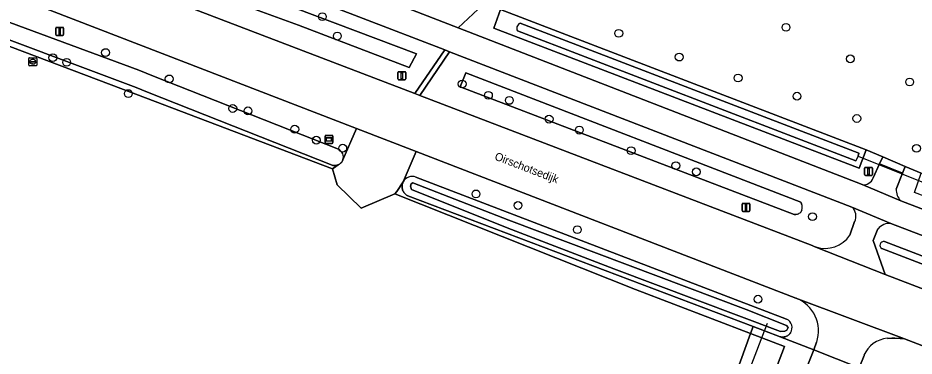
# Model space of a CAD drawing. Extents: x 155209 to 156748, y 385356 to 388487.
# Drawn here: x 155768.7 to 155880.6, y 386668.2 to 386710.5 of the extents above; entities that cross this region are included whole.
import ezdxf

# ---------------------------------------------------------------- set-up
doc = ezdxf.new("R2010")
doc.units = 0
for name, color, linetype in [('IMGEO_Afsluitpaal', 7, 'Continuous'), ('IMGEO_Berm_groen', 7, 'Continuous'), ('IMGEO_Boom', 7, 'Continuous'), ('IMGEO_Brandkraan', 7, 'Continuous'), ('IMGEO_Duiker', 7, 'Continuous'), ('IMGEO_Erf', 7, 'Continuous'), ('IMGEO_Fietspad_gesloten', 7, 'Continuous'), ('IMGEO_Gemengd_bos', 7, 'Continuous'), ('IMGEO_Groenvoorziening', 7, 'Continuous'), ('IMGEO_Haag', 7, 'Continuous'), ('IMGEO_Hek', 7, 'Continuous'), ('IMGEO_Lichtmast', 7, 'Continuous'), ('IMGEO_Oever', 7, 'Continuous'), ('IMGEO_Openbare_ruimte_label', 7, 'Continuous'), ('IMGEO_Rijbaan_lokaal_gesloten', 7, 'Continuous'), ('IMGEO_Rijbaan_lokaal_open', 7, 'Continuous'), ('IMGEO_Verkeersbordpaal', 7, 'Continuous'), ('IMGEO_Verklikker', 7, 'Continuous'), ('IMGEO_Voetpad_gesloten', 7, 'Continuous'), ('IMGEO_Voetpad_open', 7, 'Continuous'), ('IMGEO_Waterloop', 7, 'Continuous')]:
    doc.layers.add(name, color=color, linetype=linetype)

msp = doc.modelspace()

# ---------------------------------------------------------------- linework, layer by layer
at = {"layer": 'IMGEO_Afsluitpaal'}
for p, q in [((155773.4, 386708.38), (155773.4, 386709.18)), ((155773.4, 386709.18), (155773.4, 386708.38)), ((155773.5, 386709.28), (155774.29, 386709.28)), ((155774.29, 386709.28), (155773.5, 386709.28)), ((155774.39, 386709.18), (155774.39, 386708.38)), ((155774.39, 386708.38), (155774.39, 386709.18)), ((155774.29, 386708.28), (155773.5, 386708.28)), ((155773.5, 386708.28), (155774.29, 386708.28))]:
    msp.add_line(p, q, dxfattribs=at)
msp.add_lwpolyline([(155773.82, 386709.16), (155773.97, 386709.16), (155773.97, 386708.41), (155773.82, 386708.41), (155773.82, 386709.16)], dxfattribs=at)
for centre, start, end in [((155773.5, 386709.18), 90, 180), ((155773.5, 386709.18), 90, 180), ((155774.29, 386709.18), 0, 90), ((155774.29, 386709.18), 360, 90), ((155773.5, 386708.38), 180, 270), ((155773.5, 386708.38), 180, 270), ((155774.29, 386708.38), 270, 0), ((155774.29, 386708.38), 270, 0)]:
    msp.add_arc(centre, 0.1, start, end, dxfattribs=at)
at = {"layer": 'IMGEO_Berm_groen'}
msp.add_lwpolyline([(155793.53, 386723.81), (155782.08, 386727.97), (155782.52, 386725.2), (155792.56, 386721.3), (155823.67, 386709.23), (155826.78, 386712.15), (155820.02, 386714.17)], close=True, dxfattribs=at)
for points in [[(155787.54, 386712.8), (155818.26, 386701.02), (155821.98, 386706.46), (155791.39, 386718.27)], [(155785.57, 386717.88), (155790.57, 386716.13), (155803.21, 386711.7), (155818.46, 386705.97), (155817.55, 386704.28), (155803.73, 386709.57), (155789.98, 386714.61), (155785.11, 386716.4)], [(155786.7, 386706.02), (155761.51, 386715.74), (155760.31, 386714.85), (155759.25, 386713.89), (155758.81, 386713.23), (155761.07, 386712.32), (155761.11, 386712.3), (155783.77, 386703.93), (155785.63, 386703.2), (155808.7, 386694.05)], [(155828.93, 386711.51), (155826.78, 386712.15), (155823.67, 386709.23), (155874.11, 386689.65)], [(155875.47, 386690.48), (155876.27, 386692.22), (155876.68, 386693.11), (155874.62, 386693.99), (155873.73, 386691.68), (155828.11, 386709.2), (155828.93, 386711.51)], [(155809.25, 386692.73), (155810.97, 386696.65), (155786.7, 386706.02)], [(155822.58, 386706.23), (155818.86, 386700.79), (155867.85, 386682.04), (155868.04, 386681.96), (155868.31, 386681.85)], [(155872.83, 386686.83), (155822.58, 386706.23)], [(155823.91, 386701.84), (155824.61, 386703.6), (155866.46, 386687.43), (155866.53, 386687.24)], [(155866.02, 386685.97), (155865.81, 386685.92), (155865.6, 386685.89), (155823.91, 386701.84)], [(155996.82, 386644.23), (155997.61, 386646.44), (155990.99, 386649.3), (155990.06, 386646.73), (155916.52, 386675.03), (155880.66, 386688.65), (155881.47, 386691.06), (155879.46, 386691.92), (155879.13, 386691.08), (155878.35, 386689.08)], [(155878.92, 386687.63), (155990.49, 386644.88), (155995.68, 386642.88), (156000, 386641.23), (156053.62, 386620.73), (156114.7, 386597.38), (156119.19, 386595.66), (156120.94, 386594.79), (156129.23, 386591.35), (156138.31, 386587.8), (156143.99, 386585.35), (156148.25, 386583.66), (156152.28, 386581.93), (156156.65, 386579.82), (156158.6, 386579.01), (156159.45, 386578.78)], [(155866.57, 386686.46), (155866.44, 386686.22)], [(155872.58, 386683.33), (155873.16, 386685.03)], [(155989.46, 386642), (155916.39, 386670), (155877.68, 386684.79)], [(155876.08, 386684.11), (155875.47, 386682.66), (155876.97, 386678.42), (155984.6, 386637.22), (155985.42, 386636.89)], [(155876.88, 386682.53), (155987.28, 386640.17)], [(155987.28, 386640.17), (155986.9, 386639.25), (155876.58, 386681.66)]]:
    msp.add_lwpolyline(points, dxfattribs=at)
for centre, radius, start, end in [((155808.25, 386693.09), 1.07, 340.1832, 65.3376), ((155874.31, 386690.84), 1.21, 260.3353, 342.3942), ((155880.37, 386689.04), 2.03, 178.787, 224.1206), ((155865.38, 386686.79), 1.24, 344.5264, 21.3449), ((155871.8, 386685.71), 1.53, 333.3914, 47.2183), ((155865.84, 386686.76), 0.808, 282.5183, 318.1779), ((155877.52, 386682.96), 1.84, 84.9359, 141.3575), ((155869.46, 386685.43), 3.76, 252.1502, 325.9482), ((155876.79, 386682.07), 0.464, 79.3375, 242.4891)]:
    msp.add_arc(centre, radius, start, end, dxfattribs=at)
at = {"layer": 'IMGEO_Boom'}
for centre in [(155806.7, 386710.61), (155864.6, 386709.28), (155808.56, 386708.19), (155843.71, 386708.54), (155773.04, 386705.49), (155779.62, 386706.13), (155851.26, 386705.57), (155872.62, 386705.35), (155774.77, 386704.92), (155787.57, 386702.84), (155824.15, 386702.21), (155858.61, 386702.95), (155880.03, 386702.46), (155782.46, 386701.01), (155827.43, 386700.79), (155830.04, 386700.16), (155865.97, 386700.68), (155795.51, 386699.15), (155797.41, 386698.85), (155835.01, 386697.82), (155873.44, 386697.9), (155803.25, 386696.56), (155838.78, 386696.45), (155805.95, 386695.19), (155809.24, 386694.19), (155880.89, 386694.17), (155845.25, 386693.88), (155850.84, 386692.01), (155853.39, 386691.24), (155825.88, 386688.48), (155831.12, 386687.04), (155867.9, 386685.64), (155838.53, 386684.01), (155861.1, 386675.33)]:
    msp.add_circle(centre, 0.489, dxfattribs=at)
at = {"layer": 'IMGEO_Brandkraan'}
for p, q in [((155770.04, 386704.56), (155770.04, 386705.41)), ((155770.11, 386705.49), (155770.96, 386705.49)), ((155770.3, 386704.98), (155770.3, 386704.99)), ((155770.34, 386705.03), (155770.74, 386705.03)), ((155770.73, 386704.94), (155770.34, 386704.94)), ((155770.55, 386704.71), (155770.52, 386704.71)), ((155770.53, 386705.27), (155770.55, 386705.27)), ((155770.78, 386704.99), (155770.78, 386704.98)), ((155771.04, 386705.41), (155771.04, 386704.56)), ((155770.96, 386704.49), (155770.11, 386704.49))]:
    msp.add_line(p, q, dxfattribs=at)
for points in [[(155770.04, 386704.56), (155770.04, 386705.41)], [(155770.11, 386705.49), (155770.96, 386705.49)], [(155771.04, 386705.41), (155771.04, 386704.56)], [(155770.96, 386704.49), (155770.11, 386704.49)]]:
    msp.add_lwpolyline(points, dxfattribs=at)
for centre, radius, start, end in [((155770.11, 386705.41), 0.0765, 91.552, 178.448), ((155770.11, 386705.41), 0.0765, 91.552, 178.448), ((155770.34, 386704.99), 0.0403, 85.8775, 175.7526), ((155770.33, 386704.98), 0.0366, 178.938, 274.7102), ((155770.74, 386704.99), 0.043, 264.8664, 352.4533), ((155770.74, 386704.99), 0.0386, 1.7309, 96.639), ((155770.96, 386705.41), 0.0765, 1.552, 88.448), ((155770.96, 386705.41), 0.0765, 1.552, 88.448), ((155770.11, 386704.56), 0.0765, 181.552, 268.448), ((155770.11, 386704.56), 0.0765, 181.552, 268.448), ((155770.96, 386704.56), 0.0765, 271.552, 358.448), ((155770.96, 386704.56), 0.0765, 271.552, 358.448)]:
    msp.add_arc(centre, radius, start, end, dxfattribs=at)
for centre, major_axis, ratio, start_param, end_param in [((155770.52, 386704.99), (-0.387, 0.002), 0.722429, 4.712389, 7.853982), ((155770.55, 386704.99), (-0.39, 0.002), 0.717154, 1.570796, 4.712389)]:
    msp.add_ellipse(centre, major_axis=major_axis, ratio=ratio, start_param=start_param, end_param=end_param, dxfattribs=at)
at = {"layer": 'IMGEO_Duiker'}
for points in [[(155873.6, 386693.18), (155881.97, 386689.81)], [(155859.83, 386665.97), (155860.33, 386667.27), (155861.92, 386671.39), (155862.29, 386672.35)]]:
    msp.add_lwpolyline(points, dxfattribs=at)
at = {"layer": 'IMGEO_Erf'}
msp.add_lwpolyline([(155827.24, 386584.98), (155828.63, 386588.62), (155831.1, 386595.08), (155832.48, 386598.7), (155858.39, 386666.09), (155860.17, 386671.06), (155845.78, 386676.56), (155815.75, 386688.47), (155811.53, 386686.69), (155808.55, 386689.62), (155807.95, 386691.6), (155784.6, 386700.46), (155766.42, 386707.35), (155764.8, 386707.96), (155764.04, 386705.95)], dxfattribs=at)
at = {"layer": 'IMGEO_Fietspad_gesloten'}
for points in [[(155717.68, 386750), (155664.94, 386770.25), (155663.89, 386767.51), (155697.56, 386754.39), (155708.95, 386750), (155761.76, 386729.68), (155766.81, 386727.74), (155777.37, 386723.68), (155783.26, 386721.41), (155791.39, 386718.27), (155821.98, 386706.46), (155822.58, 386706.23), (155872.83, 386686.83), (155877.68, 386684.79), (155916.39, 386670), (155989.46, 386642), (155994.28, 386640.16), (156000, 386637.97), (156052.47, 386617.83), (156121.21, 386591.61), (156131.18, 386587.42), (156137.33, 386584.91), (156141.25, 386583.25)], [(156000, 386641.23), (155995.68, 386642.88), (155990.49, 386644.88), (155878.92, 386687.63), (155874.11, 386689.65), (155823.67, 386709.23), (155792.56, 386721.3), (155782.52, 386725.2), (155777.32, 386727.1), (155717.68, 386750)]]:
    msp.add_lwpolyline(points, dxfattribs=at)
at = {"layer": 'IMGEO_Gemengd_bos'}
msp.add_lwpolyline([(156143.42, 386614.27), (156125.24, 386621.36), (155846.72, 386730.89), (155826.78, 386712.15), (155828.93, 386711.51), (155874.62, 386693.99), (155876.68, 386693.11), (155879.46, 386691.92), (155881.47, 386691.06), (155990.99, 386649.3), (155997.61, 386646.44), (156055.03, 386624.31), (156120.56, 386599.32), (156137.65, 386592.62), (156152.92, 386586.26), (156153.55, 386590.46), (156160.78, 386591.55), (156161.17, 386595.64), (156158.22, 386609.07), (156157.32, 386608.64), (156155.98, 386609.71)], close=True, dxfattribs=at)
at = {"layer": 'IMGEO_Groenvoorziening'}
for points in [[(155761.07, 386712.32), (155758.81, 386713.23), (155757.43, 386711.59), (155756.9, 386710.96), (155758.83, 386710.23), (155764.8, 386707.96), (155766.42, 386707.35), (155784.6, 386700.46), (155807.95, 386691.6), (155808.36, 386691.89), (155808.67, 386692.1), (155808.59, 386692.07), (155808.5, 386692.05), (155808.4, 386692.03), (155808.31, 386692.02), (155808.21, 386692.02), (155808.12, 386692.03), (155808.02, 386692.04), (155807.93, 386692.07), (155784.87, 386701.18)], [(155784.87, 386701.18), (155783.45, 386701.75), (155760.2, 386710.46)], [(155865.84, 386675.47), (155818.43, 386693.77), (155816.8, 386689.98)], [(155818.38, 386690.59), (155864.67, 386672.83)], [(155855.14, 386636.42), (155852.27, 386637.56), (155864.42, 386669.44), (155860.17, 386671.06), (155858.39, 386666.09)], [(155865.17, 386671.16), (155865.14, 386671.11), (155865.08, 386671.03), (155865.01, 386670.95), (155864.93, 386670.88), (155864.85, 386670.82), (155864.76, 386670.76), (155864.67, 386670.71), (155864.57, 386670.67), (155864.47, 386670.64), (155864.37, 386670.62), (155864.27, 386670.61), (155864.16, 386670.61), (155864.06, 386670.61), (155863.95, 386670.63), (155863.85, 386670.65), (155868.05, 386669), (155868.42, 386669.95)], [(156047.62, 386605.62), (156000, 386623.97), (155879.41, 386670.4), (155878.87, 386670.44), (155878.19, 386670.47), (155877.79, 386670.47), (155877.25, 386670.44)], [(155874.34, 386668.32), (155873.72, 386666.78), (155876.16, 386665.82), (155876.08, 386665.9), (155876, 386665.98), (155875.94, 386666.06), (155875.88, 386666.15), (155875.83, 386666.25), (155875.79, 386666.35), (155875.76, 386666.46), (155875.73, 386666.56), (155875.72, 386666.67), (155875.72, 386666.78), (155875.72, 386666.89), (155875.74, 386666.99), (155875.77, 386667.1), (155875.8, 386667.2)]]:
    msp.add_lwpolyline(points, dxfattribs=at)
for points in [[(155817.39, 386688.23), (155817.29, 386688.28), (155817.19, 386688.34), (155817.1, 386688.41), (155817.02, 386688.49), (155816.94, 386688.58), (155816.87, 386688.67), (155816.81, 386688.77), (155816.76, 386688.87), (155816.72, 386688.98), (155816.69, 386689.09), (155816.67, 386689.2), (155816.65, 386689.31), (155816.65, 386689.43), (155816.66, 386689.54), (155816.68, 386689.65), (155816.71, 386689.76), (155816.75, 386689.87), (155816.8, 386689.98), (155815.98, 386688.8), (155815.75, 386688.47), (155845.78, 386676.56), (155860.17, 386671.06), (155860.5, 386671.92)], [(155867.81, 386668.39), (155868.05, 386669), (155863.85, 386670.65), (155861.92, 386671.39), (155860.5, 386671.92), (155860.17, 386671.06), (155864.42, 386669.44), (155852.27, 386637.56), (155855.14, 386636.42)]]:
    msp.add_lwpolyline(points, close=True, dxfattribs=at)
for centre, radius, start, end in [((155817.93, 386689.39), 1.28, 69.3648, 152.6619), ((155864.25, 386671.36), 4.41, 341.3033, 68.7987), ((155864.18, 386671.77), 1.17, 328.0144, 65.0199), ((155877.56, 386666.95), 3.51, 95.1183, 156.8896)]:
    msp.add_arc(centre, radius, start, end, dxfattribs=at)
at = {"layer": 'IMGEO_Haag'}
msp.add_lwpolyline([(155867.81, 386668.39), (155868.05, 386669), (155863.85, 386670.65), (155861.92, 386671.39), (155860.5, 386671.92), (155860.17, 386671.06), (155864.42, 386669.44), (155852.27, 386637.56), (155855.14, 386636.42)], close=True, dxfattribs=at)
at = {"layer": 'IMGEO_Hek'}
for points in [[(155766.42, 386707.35), (155784.6, 386700.46)], [(155784.6, 386700.46), (155807.95, 386691.6)], [(155807.95, 386691.6), (155808.55, 386689.62), (155811.53, 386686.69), (155815.75, 386688.47)], [(155815.75, 386688.47), (155845.78, 386676.56), (155860.17, 386671.06)]]:
    msp.add_lwpolyline(points, dxfattribs=at)
at = {"layer": 'IMGEO_Lichtmast'}
for p, q in [((155816.12, 386702.84), (155816.12, 386703.64)), ((155816.12, 386703.64), (155816.12, 386702.84)), ((155816.22, 386703.74), (155817.01, 386703.74)), ((155817.01, 386703.74), (155816.22, 386703.74)), ((155817.11, 386703.64), (155817.11, 386702.84)), ((155817.11, 386702.84), (155817.11, 386703.64)), ((155817.01, 386702.74), (155816.22, 386702.74)), ((155816.22, 386702.74), (155817.01, 386702.74)), ((155859.1, 386686.4), (155859.1, 386687.2)), ((155859.1, 386687.2), (155859.1, 386686.4)), ((155859.2, 386687.3), (155859.99, 386687.3)), ((155859.99, 386687.3), (155859.2, 386687.3)), ((155860.09, 386687.2), (155860.09, 386686.4)), ((155860.09, 386686.4), (155860.09, 386687.2)), ((155859.99, 386686.3), (155859.2, 386686.3)), ((155859.2, 386686.3), (155859.99, 386686.3))]:
    msp.add_line(p, q, dxfattribs=at)
for points in [[(155816.54, 386703.62), (155816.69, 386703.62), (155816.69, 386702.87), (155816.54, 386702.87), (155816.54, 386703.62)], [(155859.52, 386687.17), (155859.67, 386687.17), (155859.67, 386686.42), (155859.52, 386686.42), (155859.52, 386687.17)]]:
    msp.add_lwpolyline(points, dxfattribs=at)
for centre, start, end in [((155816.22, 386703.64), 90, 180), ((155816.22, 386703.64), 90, 180), ((155817.01, 386703.64), 0, 90), ((155817.01, 386703.64), 360, 90), ((155816.22, 386702.84), 180, 270), ((155816.22, 386702.84), 180, 270), ((155817.01, 386702.84), 270, 0), ((155817.01, 386702.84), 270, 0), ((155859.2, 386687.2), 90, 180), ((155859.2, 386687.2), 90, 180), ((155859.99, 386687.2), 0, 90), ((155859.99, 386687.2), 360, 90), ((155859.2, 386686.4), 180, 270), ((155859.2, 386686.4), 180, 270), ((155859.99, 386686.4), 270, 0), ((155859.99, 386686.4), 270, 0)]:
    msp.add_arc(centre, 0.1, start, end, dxfattribs=at)
at = {"layer": 'IMGEO_Oever'}
for points in [[(155828.93, 386711.51), (155828.11, 386709.2), (155873.73, 386691.68), (155874.62, 386693.99)], [(155843.09, 386679.11), (155829.79, 386684.23), (155817.81, 386689.04), (155817.7, 386689.45), (155817.78, 386689.76), (155818, 386689.88), (155830, 386685.19), (155859.63, 386674.03), (155864.66, 386672.03), (155864.87, 386671.78), (155864.7, 386671.47), (155864.45, 386671.32), (155863.92, 386671.31)]]:
    msp.add_lwpolyline(points, close=True, dxfattribs=at)
for points in [[(155831.39, 386709.8), (155873.7, 386693.58), (155873.6, 386693.18), (155873.32, 386692.6), (155831.05, 386708.84)], [(155864.67, 386672.83), (155818.38, 386690.59)], [(155816.8, 386689.98), (155816.75, 386689.87), (155816.71, 386689.76), (155816.68, 386689.65), (155816.66, 386689.54), (155816.65, 386689.43), (155816.65, 386689.31), (155816.67, 386689.2), (155816.69, 386689.09), (155816.72, 386688.98), (155816.76, 386688.87), (155816.81, 386688.77), (155816.87, 386688.67), (155816.94, 386688.58), (155817.02, 386688.49), (155817.1, 386688.41), (155817.19, 386688.34), (155817.29, 386688.28), (155817.39, 386688.23), (155860.5, 386671.92), (155861.92, 386671.39), (155863.85, 386670.65), (155863.95, 386670.63), (155864.06, 386670.61), (155864.16, 386670.61), (155864.27, 386670.61), (155864.37, 386670.62), (155864.47, 386670.64), (155864.57, 386670.67), (155864.67, 386670.71), (155864.76, 386670.76), (155864.85, 386670.82), (155864.93, 386670.88), (155865.01, 386670.95), (155865.08, 386671.03), (155865.14, 386671.11), (155865.17, 386671.16)]]:
    msp.add_lwpolyline(points, dxfattribs=at)
for centre, radius, start, end in [((155831.74, 386709.19), 0.776, 168.6587, 207.5701), ((155831.68, 386709.13), 0.73, 113.5082, 162.9912), ((155817.93, 386689.39), 1.28, 69.3648, 152.6619), ((155864.18, 386671.77), 1.17, 328.0144, 65.0199)]:
    msp.add_arc(centre, radius, start, end, dxfattribs=at)
at = {"layer": 'IMGEO_Rijbaan_lokaal_gesloten'}
for points in [[(155761.51, 386715.74), (155786.7, 386706.02), (155810.97, 386696.65), (155818.43, 386693.77), (155865.84, 386675.47), (155879.41, 386670.4), (156000, 386623.97)], [(156000, 386631.14), (155994.44, 386633.28), (155993.59, 386633.62), (155985.42, 386636.89), (155984.6, 386637.22), (155876.97, 386678.42), (155868.31, 386681.85), (155868.04, 386681.96), (155867.85, 386682.04), (155818.86, 386700.79), (155818.26, 386701.02), (155787.54, 386712.8)]]:
    msp.add_lwpolyline(points, dxfattribs=at)
at = {"layer": 'IMGEO_Rijbaan_lokaal_open'}
for points in [[(155877.25, 386670.44), (155877.79, 386670.47), (155878.19, 386670.47), (155878.87, 386670.44), (155879.41, 386670.4), (155865.84, 386675.47)], [(155868.42, 386669.95), (155868.05, 386669), (155873.72, 386666.78), (155874.34, 386668.32)]]:
    msp.add_lwpolyline(points, dxfattribs=at)
msp.add_lwpolyline([(155860.74, 386634.19), (155873.72, 386666.78), (155868.05, 386669), (155867.81, 386668.39), (155855.14, 386636.42), (155840.59, 386598.69), (155839.46, 386597.18), (155836.9, 386595.99), (155834.97, 386595.48), (155833.27, 386595.02), (155831.1, 386595.08), (155828.63, 386588.62), (155830.35, 386587.85), (155831.32, 386586.8), (155832.62, 386584.62), (155834.05, 386581.94), (155834.21, 386580.97), (155834.03, 386579.78), (155833.54, 386578.47), (155837.24, 386577.02), (155842.99, 386589.8)], close=True, dxfattribs=at)
for centre, radius, start, end in [((155864.25, 386671.36), 4.41, 341.3033, 68.7987), ((155877.56, 386666.95), 3.51, 95.1183, 156.8896)]:
    msp.add_arc(centre, radius, start, end, dxfattribs=at)
at = {"layer": 'IMGEO_Verkeersbordpaal'}
for p, q in [((155874.41, 386690.9), (155874.41, 386691.7)), ((155874.41, 386691.7), (155874.41, 386690.9)), ((155874.51, 386691.8), (155875.3, 386691.8)), ((155875.3, 386691.8), (155874.51, 386691.8)), ((155875.4, 386691.7), (155875.4, 386690.9)), ((155875.4, 386690.9), (155875.4, 386691.7)), ((155875.3, 386690.8), (155874.51, 386690.8)), ((155874.51, 386690.8), (155875.3, 386690.8))]:
    msp.add_line(p, q, dxfattribs=at)
msp.add_lwpolyline([(155874.83, 386691.67), (155874.98, 386691.67), (155874.98, 386690.92), (155874.83, 386690.92), (155874.83, 386691.67)], dxfattribs=at)
for centre, start, end in [((155874.51, 386691.7), 90, 180), ((155874.51, 386691.7), 90, 180), ((155875.3, 386691.7), 0, 90), ((155875.3, 386691.7), 360, 90), ((155874.51, 386690.9), 180, 270), ((155874.51, 386690.9), 180, 270), ((155875.3, 386690.9), 270, 0), ((155875.3, 386690.9), 270, 0)]:
    msp.add_arc(centre, 0.1, start, end, dxfattribs=at)
at = {"layer": 'IMGEO_Verklikker'}
for p, q in [((155807.03, 386694.89), (155807.03, 386695.69)), ((155807.03, 386695.69), (155807.03, 386694.89)), ((155807.13, 386695.79), (155807.92, 386695.79)), ((155807.92, 386695.79), (155807.13, 386695.79)), ((155808.02, 386695.69), (155808.02, 386694.89)), ((155808.02, 386694.89), (155808.02, 386695.69)), ((155807.92, 386694.79), (155807.13, 386694.79)), ((155807.13, 386694.79), (155807.92, 386694.79))]:
    msp.add_line(p, q, dxfattribs=at)
for points in [[(155807.13, 386695.52), (155807.91, 386695.52), (155807.91, 386695.06), (155807.13, 386695.06), (155807.13, 386695.52)], [(155807.19, 386695.46), (155807.19, 386695.12), (155807.85, 386695.12), (155807.85, 386695.46), (155807.19, 386695.46)]]:
    msp.add_lwpolyline(points, dxfattribs=at)
for centre, start, end in [((155807.13, 386695.69), 90, 180), ((155807.13, 386695.69), 90, 180), ((155807.92, 386695.69), 0, 90), ((155807.92, 386695.69), 360, 90), ((155807.13, 386694.89), 180, 270), ((155807.13, 386694.89), 180, 270), ((155807.92, 386694.89), 270, 0), ((155807.92, 386694.89), 270, 0)]:
    msp.add_arc(centre, 0.1, start, end, dxfattribs=at)
at = {"layer": 'IMGEO_Voetpad_gesloten'}
msp.add_lwpolyline([(155818.43, 386693.77), (155810.97, 386696.65), (155809.25, 386692.73), (155809.21, 386692.63), (155809.17, 386692.54), (155809.12, 386692.46), (155809.06, 386692.39), (155808.99, 386692.32), (155808.92, 386692.26), (155808.85, 386692.2), (155808.76, 386692.15), (155808.67, 386692.1), (155808.36, 386691.89), (155807.95, 386691.6), (155808.55, 386689.62), (155811.53, 386686.69), (155815.75, 386688.47), (155815.98, 386688.8), (155816.8, 386689.98)], close=True, dxfattribs=at)
at = {"layer": 'IMGEO_Voetpad_open'}
for points in [[(155821.98, 386706.46), (155818.26, 386701.02), (155818.86, 386700.79), (155822.58, 386706.23)], [(155876.68, 386693.11), (155876.27, 386692.22), (155879.13, 386691.08), (155879.46, 386691.92)]]:
    msp.add_lwpolyline(points, close=True, dxfattribs=at)
for points in [[(155878.35, 386689.08), (155879.13, 386691.08), (155876.27, 386692.22), (155875.47, 386690.48)], [(155874.11, 386689.65), (155878.92, 386687.63)], [(155877.68, 386684.79), (155872.83, 386686.83)], [(155873.16, 386685.03), (155872.58, 386683.33)], [(155868.31, 386681.85), (155876.97, 386678.42), (155875.47, 386682.66), (155876.08, 386684.11)]]:
    msp.add_lwpolyline(points, dxfattribs=at)
for centre, radius, start, end in [((155874.31, 386690.84), 1.21, 260.3353, 342.3942), ((155880.37, 386689.04), 2.03, 178.787, 224.1206), ((155871.8, 386685.71), 1.53, 333.3914, 47.2183), ((155877.52, 386682.96), 1.84, 84.9359, 141.3575), ((155869.46, 386685.43), 3.76, 252.1502, 325.9482)]:
    msp.add_arc(centre, radius, start, end, dxfattribs=at)
at = {"layer": 'IMGEO_Waterloop'}
for points in [[(155785.11, 386716.4), (155789.98, 386714.61), (155803.73, 386709.57), (155817.55, 386704.28), (155818.46, 386705.97), (155803.21, 386711.7), (155790.57, 386716.13), (155785.57, 386717.88)], [(155785.63, 386703.2), (155783.77, 386703.93), (155761.11, 386712.3), (155761.07, 386712.32)], [(155760.2, 386710.46), (155783.45, 386701.75), (155784.87, 386701.18), (155807.93, 386692.07), (155808.02, 386692.04), (155808.12, 386692.03), (155808.21, 386692.02), (155808.31, 386692.02), (155808.4, 386692.03), (155808.5, 386692.05), (155808.59, 386692.07), (155808.67, 386692.1), (155808.76, 386692.15), (155808.85, 386692.2), (155808.92, 386692.26), (155808.99, 386692.32), (155809.06, 386692.39), (155809.12, 386692.46), (155809.17, 386692.54), (155809.21, 386692.63), (155809.25, 386692.73)], [(155831.05, 386708.84), (155873.32, 386692.6), (155873.6, 386693.18), (155873.7, 386693.58), (155831.39, 386709.8)], [(155824.61, 386703.6), (155823.91, 386701.84), (155865.6, 386685.89), (155865.81, 386685.92), (155866.02, 386685.97)], [(155866.53, 386687.24), (155866.46, 386687.43), (155824.61, 386703.6)], [(155808.7, 386694.05), (155785.63, 386703.2)], [(155866.44, 386686.22), (155866.57, 386686.46)], [(155876.58, 386681.66), (155986.9, 386639.25), (155987.28, 386640.17), (155876.88, 386682.53)]]:
    msp.add_lwpolyline(points, dxfattribs=at)
msp.add_lwpolyline([(155830, 386685.19), (155818, 386689.88), (155817.78, 386689.76), (155817.7, 386689.45), (155817.81, 386689.04), (155829.79, 386684.23), (155843.09, 386679.11), (155863.92, 386671.31), (155864.45, 386671.32), (155864.7, 386671.47), (155864.87, 386671.78), (155864.66, 386672.03), (155859.63, 386674.03)], close=True, dxfattribs=at)
for centre, radius, start, end in [((155831.74, 386709.19), 0.776, 168.6587, 207.5701), ((155831.68, 386709.13), 0.73, 113.5082, 162.9912), ((155808.25, 386693.09), 1.07, 340.1832, 65.3376), ((155865.38, 386686.79), 1.24, 344.5264, 21.3449), ((155865.84, 386686.76), 0.808, 282.5183, 318.1779), ((155876.79, 386682.07), 0.464, 79.3375, 242.4891)]:
    msp.add_arc(centre, radius, start, end, dxfattribs=at)

# ---------------------------------------------------------------- texts
at = {"layer": 'IMGEO_Openbare_ruimte_label'}
msp.add_text('Oirschotsedijk', height=1, rotation=339.0283, dxfattribs=at).set_placement((155828.12, 386692.79))

doc.saveas('drawing.dxf')
